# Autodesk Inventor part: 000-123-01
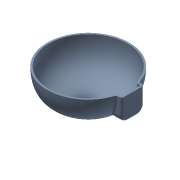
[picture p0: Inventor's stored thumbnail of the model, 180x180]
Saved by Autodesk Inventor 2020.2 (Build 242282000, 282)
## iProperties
Created: 2011-11
Part Number: 000-123-01
Material: Ogólny
Document SubType Name: Modeling
Designer: F.Stasiak
Density: 1 g/cm^3
Appearance: Stalowoniebieska - jasna
Manager: www.cadconsulting.pl
Company: Fabian Stasiak CAD Consulting
Author: F.Stasiak
Subject: Zbiór ćwiczeń. Autodesk Inventor 2020. Kurs podstawowy
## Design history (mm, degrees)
sketch "Szkic3"
  geometry: L1 (-15.967, -40.01)-(-15.967, -64.387); L2 (-15.967, -52.198)-(2.162, -52.198); L3 (2.162, -52.198)-(2.162, 17.802); L4 (2.162, 17.802)-(-70.655, 17.802); L5 (-70.655, 28.209)-(-70.655, 7.395); A1 r 23.094 centre (-39.061, -52.198) between (-17.786, -61.181) and (-17.786, -43.215); A2 r 101.464 centre (30.81, 17.802) between (-70.315, 26.099) and (-70.315, 9.504); 3 further points
  constraints: 10 end point, 4 midpoint, 4 vertical, 2 centre point, 2 point on circle, 1 horizontal, 1 parallel, 1 perpendicular, 6 other
  dimensions: "d13" = 70 distance of L2.end L3.end
revolve "Obrót1" sketch "Szkic3" stored, may be unused: angle "d14" = 90 deg
fillet "Zaokrąglenie4" dims "d15" = 5
sketch "Szkic4"
  geometry: L1 (72.817, 17.802)-(-72.817, 17.802) reference; L2 (-20, 17.802)-(20, 17.802); L3 (20, 17.802)-(20, -22.198); L4 (20, -22.198)-(-20, -22.198); L5 (-20, -22.198)-(-20, 17.802); 3 further points
  constraints: 8 end point, 2 midpoint, 2 parallel, 1 horizontal, 1 perpendicular, 1 point on line
  dimensions: "d17" = 40 distance of L3.end L4.end; "d18" = 40 distance of L2.end L3.end
extrude "Wyciągnięcie proste3" join sketch "Szkic4" distance "d19" = 77; taper "d20" = 0 deg
fillet "Zaokrąglenie5" dims "d21" = 12
fillet "Zaokrąglenie6" dims "d22" = 4
fillet "Zaokrąglenie7" dims "d23" = 4
feature "Skorupa2" dims "d16" = 3
node "Bryła2"
